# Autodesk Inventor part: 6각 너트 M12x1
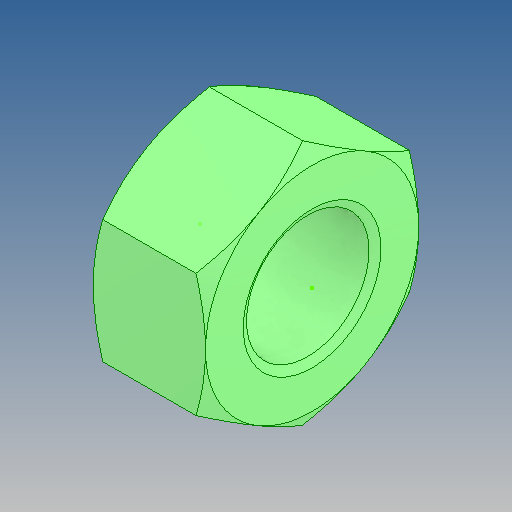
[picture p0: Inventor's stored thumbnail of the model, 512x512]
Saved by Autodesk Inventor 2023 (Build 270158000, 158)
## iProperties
Created: 2025-04
Part Number: 6각 너트 M12x1
Material: 강철, 연강
Description: 6각 너트
Document SubType Name: Modeling
Designer: Admin
Density: 7.85 g/cm^3
Appearance: 기본값
Author: jhkim
Sending System: Autodesk Inventor 2026
Preprocessor: ST-DEVELOPER v20.1
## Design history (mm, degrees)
node "6각 너트 M12x11"
  node "스케치1"
node "스케치3"
node "솔리드1"
body "Solid1"
